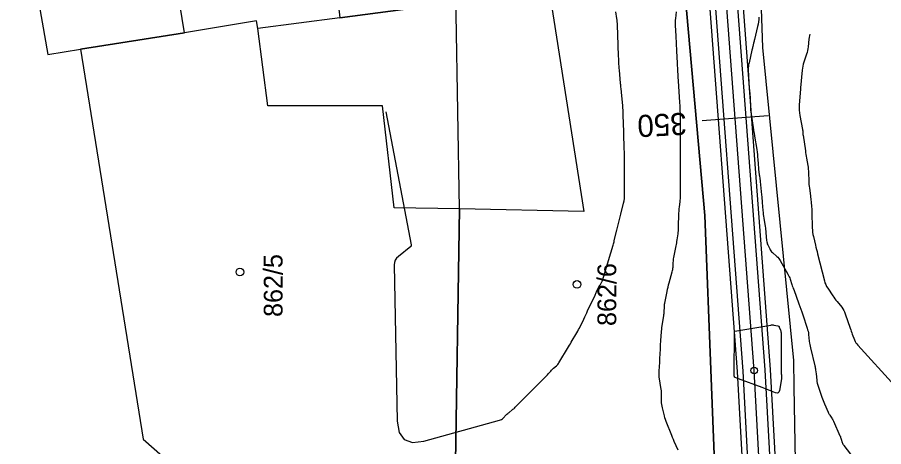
# Model space of a CAD drawing. Extents: x -534481 to -534262, y -1190577 to -1190138.
# Drawn here: x -534376.21 to -534337, y -1190230.07 to -1190210.64 of the extents above; entities that cross this region are included whole.
import ezdxf

# ---------------------------------------------------------------- set-up
doc = ezdxf.new("R2010")
doc.units = 0
for name, color, linetype in [('Bonity', 7, 'Continuous'), ('Definiční body', 7, 'Continuous'), ('Polygon budovy', 7, 'Continuous'), ('Polygon parcely', 7, 'Continuous'), ('Vrstva 18', 7, 'Continuous'), ('Vrstva 19', 7, 'Continuous'), ('Vrstva 31', 7, 'Continuous'), ('Vrstva 35', 7, 'Continuous'), ('Vrstva 37', 7, 'Continuous'), ('Vrstva 46', 7, 'Continuous')]:
    doc.layers.add(name, color=color, linetype=linetype)

msp = doc.modelspace()

# ---------------------------------------------------------------- linework, layer by layer
at = {"layer": 'Bonity'}
msp.add_lwpolyline([(-534342.428, -1190234.65), (-534342.865, -1190226.62), (-534344.323, -1190207.198), (-534345.257, -1190192.285), (-534345.89, -1190175.458), (-534346.05, -1190156.962), (-534344.257, -1190151.926), (-534342.463, -1190149.215)], dxfattribs=at)
at = {"layer": 'Definiční body'}
for points in [[(-534340.96, -1190232.41), (-534341.05, -1190227.37), (-534341.07, -1190226.16), (-534342.47, -1190212), (-534343.03, -1190195.73), (-534343.24, -1190185.5)], [(-534347.19, -1190196.18), (-534346.8, -1190200.49), (-534345.1, -1190219.6), (-534344.81, -1190226.96), (-534344.61, -1190231.96)], [(-534356.39, -1190231.73), (-534356.2, -1190219.31), (-534356.58, -1190197.27)], [(-534359.11, -1190201.91), (-534358.74, -1190210.28), (-534361.62, -1190210.66), (-534365.33, -1190211.15), (-534365.38, -1190210.8), (-534368.64, -1190211.34), (-534373.35, -1190212.08)], [(-534376.21, -1190204.38), (-534374.83, -1190212.32), (-534373.35, -1190212.08)], [(-534373.35, -1190212.08), (-534370.52, -1190229.73), (-534368.51, -1190231.49), (-534357.69, -1190231.7), (-534356.39, -1190231.73)]]:
    msp.add_lwpolyline(points, dxfattribs=at)
at = {"layer": 'Polygon parcely'}
for points in [[(-534356.39, -1190231.73), (-534347.08, -1190231.91), (-534344.61, -1190231.96), (-534344.81, -1190226.96), (-534345.1, -1190219.6), (-534346.8, -1190200.49), (-534353.41, -1190201.32), (-534350.57, -1190219.42), (-534356.2, -1190219.31)], [(-534374.83, -1190204.15), (-534376.21, -1190204.38), (-534374.83, -1190212.32), (-534373.35, -1190212.08), (-534368.64, -1190211.34), (-534369.15, -1190208.17), (-534369.02, -1190208.12), (-534369.05, -1190207.85), (-534364.11, -1190207.12), (-534364.16, -1190206.82), (-534362.08, -1190206.54), (-534361.62, -1190210.66), (-534358.74, -1190210.28), (-534359.11, -1190201.91), (-534361.27, -1190202.22), (-534368.34, -1190203.23)], [(-534370.52, -1190229.73), (-534368.51, -1190231.49), (-534357.69, -1190231.7), (-534356.39, -1190231.73), (-534356.2, -1190219.31), (-534359.16, -1190219.26), (-534359.68, -1190214.65), (-534364.87, -1190214.64), (-534365.33, -1190211.15), (-534365.38, -1190210.8), (-534368.64, -1190211.34), (-534373.35, -1190212.08)]]:
    msp.add_lwpolyline(points, close=True, dxfattribs=at)
at = {"layer": 'Vrstva 18'}
for points in [[(-534346.3, -1190230.218), (-534346.475, -1190229.825), (-534346.512, -1190229.739), (-534346.55, -1190229.652), (-534346.586, -1190229.565), (-534346.622, -1190229.478), (-534346.813, -1190229.009), (-534346.845, -1190228.926), (-534346.874, -1190228.843), (-534346.9, -1190228.758), (-534346.924, -1190228.672), (-534347.016, -1190228.305), (-534347.032, -1190228.23), (-534347.044, -1190228.154), (-534347.051, -1190228.077), (-534347.054, -1190228), (-534347.054, -1190227.689), (-534347.055, -1190227.612), (-534347.06, -1190227.535), (-534347.068, -1190227.458), (-534347.079, -1190227.381), (-534347.144, -1190226.996), (-534347.154, -1190226.92), (-534347.16, -1190226.844), (-534347.162, -1190226.768), (-534347.16, -1190226.692), (-534347.141, -1190226.386), (-534347.136, -1190226.309), (-534347.132, -1190226.233), (-534347.128, -1190226.156), (-534347.125, -1190226.08), (-534347.106, -1190225.65), (-534347.102, -1190225.57), (-534347.098, -1190225.489), (-534347.093, -1190225.408), (-534347.088, -1190225.328), (-534347.068, -1190225.006), (-534347.062, -1190224.925), (-534347.054, -1190224.845), (-534347.045, -1190224.765), (-534347.034, -1190224.685), (-534346.951, -1190224.131), (-534346.945, -1190224.085), (-534346.94, -1190224.038), (-534346.936, -1190223.992), (-534346.934, -1190223.945), (-534346.926, -1190223.758), (-534346.924, -1190223.712), (-534346.919, -1190223.665), (-534346.913, -1190223.619), (-534346.905, -1190223.573), (-534346.803, -1190223.047), (-534346.782, -1190222.946), (-534346.759, -1190222.846), (-534346.734, -1190222.745), (-534346.707, -1190222.646), (-534346.567, -1190222.153), (-534346.554, -1190222.101), (-534346.544, -1190222.049), (-534346.537, -1190221.996), (-534346.533, -1190221.942), (-534346.523, -1190221.727), (-534346.519, -1190221.673), (-534346.514, -1190221.619), (-534346.506, -1190221.566), (-534346.497, -1190221.513), (-534346.392, -1190220.979), (-534346.38, -1190220.912), (-534346.368, -1190220.844), (-534346.356, -1190220.777), (-534346.346, -1190220.709), (-534346.305, -1190220.438), (-534346.296, -1190220.37), (-534346.289, -1190220.302), (-534346.284, -1190220.234), (-534346.281, -1190220.165), (-534346.263, -1190219.491), (-534346.26, -1190219.426), (-534346.256, -1190219.361), (-534346.251, -1190219.296), (-534346.244, -1190219.232), (-534346.213, -1190218.974), (-534346.206, -1190218.909), (-534346.201, -1190218.844), (-534346.198, -1190218.779), (-534346.197, -1190218.715), (-534346.197, -1190215.208), (-534346.198, -1190215.026), (-534346.203, -1190214.845), (-534346.21, -1190214.663), (-534346.22, -1190214.481), (-534346.282, -1190213.529), (-534346.295, -1190213.324), (-534346.318, -1190212.981), (-534346.322, -1190212.913), (-534346.326, -1190212.844), (-534346.33, -1190212.776), (-534346.333, -1190212.707), (-534346.36, -1190212.154), (-534346.393, -1190211.494), (-534346.418, -1190210.999), (-534346.42, -1190210.922), (-534346.419, -1190210.845), (-534346.415, -1190210.768), (-534346.408, -1190210.691), (-534346.375, -1190210.383)], [(-534342.644, -1190210.625), (-534342.651, -1190210.734), (-534342.663, -1190210.843), (-534342.681, -1190210.951), (-534342.704, -1190211.058), (-534342.847, -1190211.642), (-534342.857, -1190211.681), (-534342.866, -1190211.721), (-534342.875, -1190211.761), (-534342.885, -1190211.801), (-534342.921, -1190211.961), (-534342.93, -1190212.001), (-534342.94, -1190212.041), (-534342.949, -1190212.081), (-534342.959, -1190212.121), (-534343.094, -1190212.691), (-534343.11, -1190212.768), (-534343.121, -1190212.846), (-534343.126, -1190212.924), (-534343.126, -1190213.003), (-534343.116, -1190213.319), (-534343.112, -1190213.398), (-534343.108, -1190213.477), (-534343.103, -1190213.556), (-534343.096, -1190213.635), (-534343.065, -1190213.983), (-534343.058, -1190214.067), (-534343.052, -1190214.151), (-534343.048, -1190214.236), (-534343.045, -1190214.32), (-534343.034, -1190214.671), (-534343.03, -1190214.758), (-534343.024, -1190214.844), (-534343.014, -1190214.93), (-534343.002, -1190215.016), (-534342.905, -1190215.628), (-534342.9, -1190215.661), (-534342.894, -1190215.693), (-534342.889, -1190215.726), (-534342.884, -1190215.758), (-534342.862, -1190215.888), (-534342.857, -1190215.92), (-534342.851, -1190215.953), (-534342.846, -1190215.985), (-534342.841, -1190216.018), (-534342.747, -1190216.623), (-534342.73, -1190216.734), (-534342.716, -1190216.845), (-534342.704, -1190216.957), (-534342.694, -1190217.068), (-534342.644, -1190217.675), (-534342.64, -1190217.707), (-534342.637, -1190217.739), (-534342.632, -1190217.772), (-534342.627, -1190217.804), (-534342.604, -1190217.931), (-534342.598, -1190217.963), (-534342.593, -1190217.996), (-534342.589, -1190218.028), (-534342.586, -1190218.06), (-534342.526, -1190218.667), (-534342.517, -1190218.756), (-534342.509, -1190218.845), (-534342.502, -1190218.933), (-534342.495, -1190219.022), (-534342.468, -1190219.382), (-534342.46, -1190219.469), (-534342.451, -1190219.556), (-534342.44, -1190219.642), (-534342.427, -1190219.728), (-534342.367, -1190220.097), (-534342.355, -1190220.171), (-534342.345, -1190220.246), (-534342.336, -1190220.32), (-534342.329, -1190220.395), (-534342.298, -1190220.743), (-534342.291, -1190220.793), (-534342.28, -1190220.842), (-534342.265, -1190220.89), (-534342.245, -1190220.937), (-534342.156, -1190221.121), (-534342.132, -1190221.165), (-534342.103, -1190221.207), (-534342.071, -1190221.245), (-534342.035, -1190221.28), (-534341.835, -1190221.456), (-534341.791, -1190221.498), (-534341.751, -1190221.544), (-534341.715, -1190221.592), (-534341.683, -1190221.644), (-534341.331, -1190222.263), (-534341.302, -1190222.318), (-534341.276, -1190222.374), (-534341.252, -1190222.431), (-534341.232, -1190222.49), (-534341.155, -1190222.726), (-534341.136, -1190222.785), (-534341.116, -1190222.844), (-534341.095, -1190222.903), (-534341.073, -1190222.961), (-534340.835, -1190223.598), (-534340.79, -1190223.722), (-534340.746, -1190223.846), (-534340.703, -1190223.97), (-534340.661, -1190224.095), (-534340.463, -1190224.7), (-534340.441, -1190224.773), (-534340.423, -1190224.846), (-534340.409, -1190224.921), (-534340.399, -1190224.996), (-534340.366, -1190225.299), (-534340.356, -1190225.375), (-534340.344, -1190225.45), (-534340.33, -1190225.524), (-534340.313, -1190225.598), (-534340.113, -1190226.41), (-534340.103, -1190226.453), (-534340.094, -1190226.496), (-534340.087, -1190226.539), (-534340.08, -1190226.583), (-534340.053, -1190226.774), (-534340.049, -1190226.81), (-534340.045, -1190226.845), (-534340.041, -1190226.88), (-534340.039, -1190226.915), (-534340.03, -1190227.056), (-534340.026, -1190227.091), (-534340.021, -1190227.126), (-534340.013, -1190227.16), (-534340.003, -1190227.194), (-534339.795, -1190227.824), (-534339.768, -1190227.901), (-534339.74, -1190227.978), (-534339.709, -1190228.054), (-534339.677, -1190228.13), (-534339.512, -1190228.508), (-534339.495, -1190228.544), (-534339.476, -1190228.579), (-534339.456, -1190228.613), (-534339.435, -1190228.647), (-534339.345, -1190228.779), (-534339.324, -1190228.812), (-534339.304, -1190228.846), (-534339.285, -1190228.881), (-534339.268, -1190228.917), (-534338.977, -1190229.57), (-534338.961, -1190229.607), (-534338.947, -1190229.644), (-534338.933, -1190229.682), (-534338.921, -1190229.721), (-534338.875, -1190229.875), (-534338.861, -1190229.913), (-534338.845, -1190229.949), (-534338.825, -1190229.984), (-534338.802, -1190230.017), (-534338.308, -1190230.661)]]:
    msp.add_lwpolyline(points, dxfattribs=at)
at = {"layer": 'Vrstva 19'}
for points in [[(-534359.53, -1190214.922), (-534358.38, -1190220.935), (-534358.379, -1190220.942), (-534358.379, -1190220.949), (-534358.38, -1190220.957), (-534358.382, -1190220.964), (-534358.39, -1190220.992), (-534358.392, -1190220.999), (-534358.396, -1190221.005), (-534358.4, -1190221.011), (-534358.405, -1190221.015), (-534358.964, -1190221.454), (-534359.047, -1190221.534), (-534359.106, -1190221.626), (-534359.14, -1190221.729), (-534359.15, -1190221.845), (-534359.013, -1190228.914), (-534358.929, -1190229.427), (-534358.702, -1190229.748), (-534358.33, -1190229.875), (-534357.814, -1190229.811), (-534354.382, -1190228.87), (-534354.337, -1190228.855), (-534354.295, -1190228.834), (-534354.257, -1190228.807), (-534354.222, -1190228.776), (-534354.081, -1190228.632), (-534354.049, -1190228.601), (-534354.017, -1190228.571), (-534353.984, -1190228.541), (-534353.95, -1190228.513), (-534353.812, -1190228.403), (-534353.778, -1190228.375), (-534353.745, -1190228.346), (-534353.712, -1190228.316), (-534353.681, -1190228.285), (-534352.302, -1190226.907), (-534352.272, -1190226.875), (-534352.241, -1190226.843), (-534352.212, -1190226.811), (-534352.183, -1190226.777), (-534352.069, -1190226.643), (-534352.04, -1190226.61), (-534352.01, -1190226.578), (-534351.978, -1190226.548), (-534351.945, -1190226.518), (-534351.81, -1190226.404), (-534351.778, -1190226.375), (-534351.749, -1190226.343), (-534351.722, -1190226.308), (-534351.698, -1190226.272), (-534351.266, -1190225.547), (-534351.224, -1190225.476), (-534351.181, -1190225.406), (-534351.139, -1190225.336), (-534351.096, -1190225.265), (-534350.925, -1190224.985), (-534350.883, -1190224.914), (-534350.843, -1190224.843), (-534350.805, -1190224.77), (-534350.769, -1190224.696), (-534350.573, -1190224.289), (-534350.529, -1190224.196), (-534350.485, -1190224.103), (-534350.441, -1190224.01), (-534350.397, -1190223.917), (-534350.064, -1190223.204), (-534350.048, -1190223.168), (-534350.031, -1190223.132), (-534350.014, -1190223.096), (-534349.997, -1190223.06), (-534349.907, -1190222.869), (-534349.901, -1190222.857), (-534349.894, -1190222.845), (-534349.888, -1190222.833), (-534349.88, -1190222.821), (-534349.851, -1190222.775), (-534349.844, -1190222.763), (-534349.836, -1190222.751), (-534349.829, -1190222.74), (-534349.822, -1190222.728), (-534349.766, -1190222.634), (-534349.755, -1190222.614), (-534349.746, -1190222.593), (-534349.737, -1190222.572), (-534349.73, -1190222.551), (-534349.353, -1190221.3), (-534349.247, -1190220.946), (-534349.232, -1190220.895), (-534349.217, -1190220.844), (-534349.204, -1190220.793), (-534349.191, -1190220.742), (-534349.073, -1190220.264), (-534349.058, -1190220.204), (-534349.043, -1190220.145), (-534349.028, -1190220.085), (-534349.012, -1190220.025), (-534348.95, -1190219.787), (-534348.935, -1190219.728), (-534348.92, -1190219.668), (-534348.905, -1190219.608), (-534348.891, -1190219.549), (-534348.772, -1190219.05), (-534348.75, -1190218.947), (-534348.735, -1190218.843), (-534348.726, -1190218.738), (-534348.723, -1190218.633), (-534348.726, -1190217.87), (-534348.726, -1190217.819), (-534348.729, -1190217.09), (-534348.73, -1190216.967), (-534348.732, -1190216.845), (-534348.734, -1190216.722), (-534348.738, -1190216.599), (-534348.759, -1190215.87), (-534348.76, -1190215.852), (-534348.761, -1190215.83), (-534348.762, -1190215.817), (-534348.786, -1190215.063), (-534348.79, -1190214.954), (-534348.796, -1190214.845), (-534348.803, -1190214.735), (-534348.812, -1190214.626), (-534348.864, -1190214.044), (-534348.867, -1190214.008), (-534348.871, -1190213.972), (-534348.875, -1190213.936), (-534348.878, -1190213.9), (-534348.894, -1190213.757), (-534348.898, -1190213.721), (-534348.902, -1190213.686), (-534348.905, -1190213.65), (-534348.909, -1190213.614), (-534348.963, -1190213.027), (-534348.971, -1190212.936), (-534348.978, -1190212.844), (-534348.983, -1190212.753), (-534348.988, -1190212.661), (-534349.005, -1190212.25), (-534349.008, -1190212.181), (-534349.01, -1190212.112), (-534349.012, -1190212.043), (-534349.014, -1190211.975), (-534349.022, -1190211.7), (-534349.024, -1190211.631), (-534349.026, -1190211.562), (-534349.028, -1190211.493), (-534349.031, -1190211.425), (-534349.048, -1190210.996), (-534349.052, -1190210.921), (-534349.058, -1190210.845), (-534349.066, -1190210.769), (-534349.076, -1190210.694), (-534349.119, -1190210.393)], [(-534340.345, -1190211.396), (-534340.359, -1190211.466), (-534340.371, -1190211.544), (-534340.381, -1190211.624), (-534340.42, -1190211.977), (-534340.432, -1190212.062), (-534340.448, -1190212.146), (-534340.469, -1190212.229), (-534340.494, -1190212.311), (-534340.615, -1190212.67), (-534340.642, -1190212.758), (-534340.663, -1190212.847), (-534340.679, -1190212.937), (-534340.69, -1190213.028), (-534340.757, -1190213.822), (-534340.758, -1190213.838), (-534340.76, -1190213.865), (-534340.76, -1190213.869), (-534340.821, -1190214.611), (-534340.827, -1190214.728), (-534340.824, -1190214.844), (-534340.814, -1190214.959), (-534340.795, -1190215.074), (-534340.669, -1190215.721), (-534340.666, -1190215.742), (-534340.663, -1190215.763), (-534340.661, -1190215.784), (-534340.66, -1190215.805), (-534340.657, -1190215.89), (-534340.656, -1190215.911), (-534340.654, -1190215.932), (-534340.652, -1190215.953), (-534340.649, -1190215.974), (-534340.545, -1190216.678), (-534340.532, -1190216.761), (-534340.519, -1190216.844), (-534340.506, -1190216.928), (-534340.492, -1190217.011), (-534340.436, -1190217.343), (-534340.423, -1190217.426), (-534340.413, -1190217.51), (-534340.406, -1190217.594), (-534340.402, -1190217.678), (-534340.389, -1190218.042), (-534340.386, -1190218.123), (-534340.38, -1190218.203), (-534340.372, -1190218.284), (-534340.362, -1190218.364), (-534340.315, -1190218.719), (-534340.307, -1190218.782), (-534340.299, -1190218.845), (-534340.292, -1190218.907), (-534340.285, -1190218.97), (-534340.259, -1190219.222), (-534340.254, -1190219.285), (-534340.249, -1190219.348), (-534340.246, -1190219.411), (-534340.244, -1190219.474), (-534340.229, -1190220.163), (-534340.224, -1190220.263), (-534340.214, -1190220.362), (-534340.199, -1190220.46), (-534340.179, -1190220.558), (-534340.087, -1190220.948), (-534340.064, -1190221.045), (-534340.041, -1190221.143), (-534340.017, -1190221.24), (-534339.992, -1190221.337), (-534339.684, -1190222.555), (-534339.657, -1190222.645), (-534339.623, -1190222.733), (-534339.581, -1190222.817), (-534339.532, -1190222.898), (-534339.308, -1190223.233), (-534339.261, -1190223.302), (-534339.212, -1190223.37), (-534339.161, -1190223.436), (-534339.109, -1190223.502), (-534338.895, -1190223.76), (-534338.845, -1190223.827), (-534338.802, -1190223.897), (-534338.765, -1190223.971), (-534338.735, -1190224.049), (-534338.515, -1190224.711), (-534338.492, -1190224.778), (-534338.469, -1190224.844), (-534338.444, -1190224.91), (-534338.42, -1190224.976), (-534338.318, -1190225.238), (-534338.29, -1190225.302), (-534338.257, -1190225.362), (-534338.218, -1190225.419), (-534338.173, -1190225.473), (-534336.493, -1190227.306)]]:
    msp.add_lwpolyline(points, dxfattribs=at)
msp.add_lwpolyline([(-534341.621, -1190226.953), (-534341.621, -1190226.968), (-534341.622, -1190226.984), (-534341.624, -1190226.999), (-534341.716, -1190227.531), (-534341.737, -1190227.598), (-534341.774, -1190227.637), (-534341.827, -1190227.648), (-534341.895, -1190227.632), (-534342.198, -1190227.511), (-534342.274, -1190227.481), (-534342.35, -1190227.451), (-534342.426, -1190227.422), (-534342.502, -1190227.394), (-534343.573, -1190226.993), (-534343.607, -1190226.981), (-534343.641, -1190226.968), (-534343.727, -1190226.934), (-534343.735, -1190226.931), (-534343.74, -1190226.926), (-534343.745, -1190226.92), (-534343.748, -1190226.912), (-534343.762, -1190226.866), (-534343.767, -1190226.849), (-534343.769, -1190226.844), (-534343.769, -1190226.839), (-534343.768, -1190226.82), (-534343.768, -1190226.813), (-534343.748, -1190224.85), (-534343.747, -1190224.843), (-534343.744, -1190224.835), (-534343.742, -1190224.833), (-534343.737, -1190224.836), (-534343.734, -1190224.837), (-534342.112, -1190224.562), (-534342.075, -1190224.558), (-534342.038, -1190224.557), (-534342.001, -1190224.559), (-534341.964, -1190224.565), (-534341.787, -1190224.602), (-534341.767, -1190224.609), (-534341.75, -1190224.619), (-534341.736, -1190224.634), (-534341.726, -1190224.653), (-534341.682, -1190224.76), (-534341.678, -1190224.768), (-534341.675, -1190224.776), (-534341.672, -1190224.785), (-534341.669, -1190224.793), (-534341.658, -1190224.827), (-534341.656, -1190224.836), (-534341.653, -1190224.845), (-534341.652, -1190224.853), (-534341.651, -1190224.862), (-534341.644, -1190224.921), (-534341.643, -1190224.934), (-534341.642, -1190224.946), (-534341.641, -1190224.959), (-534341.641, -1190224.972), (-534341.641, -1190226.717), (-534341.641, -1190226.73), (-534341.64, -1190226.743), (-534341.639, -1190226.755), (-534341.638, -1190226.768), (-534341.631, -1190226.819), (-534341.629, -1190226.832), (-534341.628, -1190226.845), (-534341.626, -1190226.857), (-534341.625, -1190226.87), (-534341.621, -1190226.938)], close=True, dxfattribs=at)
at = {"layer": 'Vrstva 31'}
msp.add_lwpolyline([(-534342.226, -1190215.093), (-534345.218, -1190215.318)], dxfattribs=at)
at = {"layer": 'Vrstva 35'}
for points in [[(-534343.317, -1190232.109), (-534343.613, -1190226.668), (-534345.072, -1190207.25), (-534346.006, -1190192.323), (-534346.64, -1190175.475), (-534346.801, -1190156.835), (-534344.933, -1190151.588), (-534343.268, -1190149.073)], [(-534343.067, -1190232.098), (-534343.364, -1190226.652), (-534344.822, -1190207.233), (-534345.756, -1190192.31), (-534346.39, -1190175.47), (-534346.551, -1190156.878), (-534344.708, -1190151.701), (-534343, -1190149.12)], [(-534342.068, -1190232.057), (-534342.366, -1190226.587), (-534343.825, -1190207.164), (-534344.757, -1190192.26), (-534345.39, -1190175.446), (-534345.55, -1190157.046), (-534343.807, -1190152.151), (-534341.926, -1190149.309)], [(-534341.818, -1190232.046), (-534342.116, -1190226.571), (-534343.575, -1190207.147), (-534344.507, -1190192.248), (-534345.14, -1190175.441), (-534345.299, -1190157.088), (-534343.581, -1190152.264), (-534341.657, -1190149.357)]]:
    msp.add_lwpolyline(points, dxfattribs=at)
at = {"layer": 'Vrstva 37'}
msp.add_circle((-534342.865, -1190226.62), 0.15, dxfattribs=at)
msp.add_circle((-534342.865, -1190226.62), 0.15, dxfattribs=at)
msp.add_circle((-534342.865, -1190226.62), 0.15, dxfattribs=at)
msp.add_circle((-534342.865, -1190226.62), 0.15, dxfattribs=at)
msp.add_circle((-534342.865, -1190226.62), 0.15, dxfattribs=at)
msp.add_circle((-534342.865, -1190226.62), 0.15, dxfattribs=at)
at = {"layer": 'Vrstva 46'}
for centre in [(-534366.136, -1190222.163), (-534350.877, -1190222.724)]:
    msp.add_circle(centre, 0.175, dxfattribs=at)

# ---------------------------------------------------------------- texts
at = {"layer": 'Polygon budovy'}
for s, p in [('862/5', (-534364.205, -1190224.196)), ('862/6', (-534349.103, -1190224.605))]:
    msp.add_text(s, height=0.85, rotation=90, dxfattribs=at).set_placement(p)
at = {"layer": 'Vrstva 31'}
msp.add_text('350', height=1, rotation=183.0689, dxfattribs=at).set_placement((-534345.945, -1190214.949))

doc.saveas('drawing.dxf')
